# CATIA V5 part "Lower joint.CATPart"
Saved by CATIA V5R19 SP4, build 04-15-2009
Part number: Lower joint
Bounding box of the stored display mesh (mm): x 0 to 530, y -20 to 20, z -12.5 to 12.5
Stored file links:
  G:\EU_thinkMotion\CFAO_2010\MMS_groupe1\MMS_groupe1\OK\ptangsittisin\TANGSITTISIN\TANGSITTISIN\Lower joint.CATPart
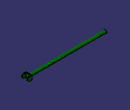
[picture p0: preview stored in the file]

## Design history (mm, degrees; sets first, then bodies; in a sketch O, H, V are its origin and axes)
Body1 (main body)
  Sketch1 on yz-plane, origin (0, 0, 0), H (0, 1, 0), V (0, 0, 1)
    circle A1 centre (0, 0) radius 10
    radius A1 = 10
  Pad1: profile Sketch1, direction (1, 0, 0), length 500
  Sketch2 on end face of Pad1, origin (500, 0, 0), H (0, 1, 0), V (0, 0, 1)
    line L1 (-20, 12.5) -> (20, 12.5)
    line L2 (20, 12.5) -> (20, -12.5)
    line L3 (20, -12.5) -> (-20, -12.5)
    line L4 (-20, -12.5) -> (-20, 12.5)
    length L2 = 25
    distance H L1 = 12.5
  Pad2: profile Sketch2, direction (1, 0, 0), length 30
  Sketch3 on face of Pad2 from Sketch2.L3, origin (0, 0, -12.5), H (1, 0, 0), V (0, -1, 0)
    reference projected curve E1 from face of Pad2 from Sketch2.L3
    line L1 (505, 15) -> (530, 15)
    line L2 (530, 15) -> (530, -15)
    line L3 (530, -15) -> (505, -15)
    line L4 (505, -15) -> (505, 15)
    length L4 = 30
    distance L1 H = 15
    length L3 = 25
    distance L2 E1 = 0
    length L1 = 25
  Pocket1: profile Sketch3, direction (0, 0, 1), through (limit type 6)
  Fillet1: radius 12.5, on edge [face of Pad2 from Sketch2.L1 | end face of Pad2] (x2); edge [face of Pad2 from Sketch2.L3 | end face of Pad2] (x2)
  Sketch4 on face of Pad2 from Sketch2.L4, origin (0, -20, 0), H (1, 0, 0), V (0, 0, 1)
    circle A1 centre (167.5, 0) radius 2.5
    radius A1 = 2.5
  Pocket2: profile Sketch4, direction (0, 1, 0), through (limit type 3)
